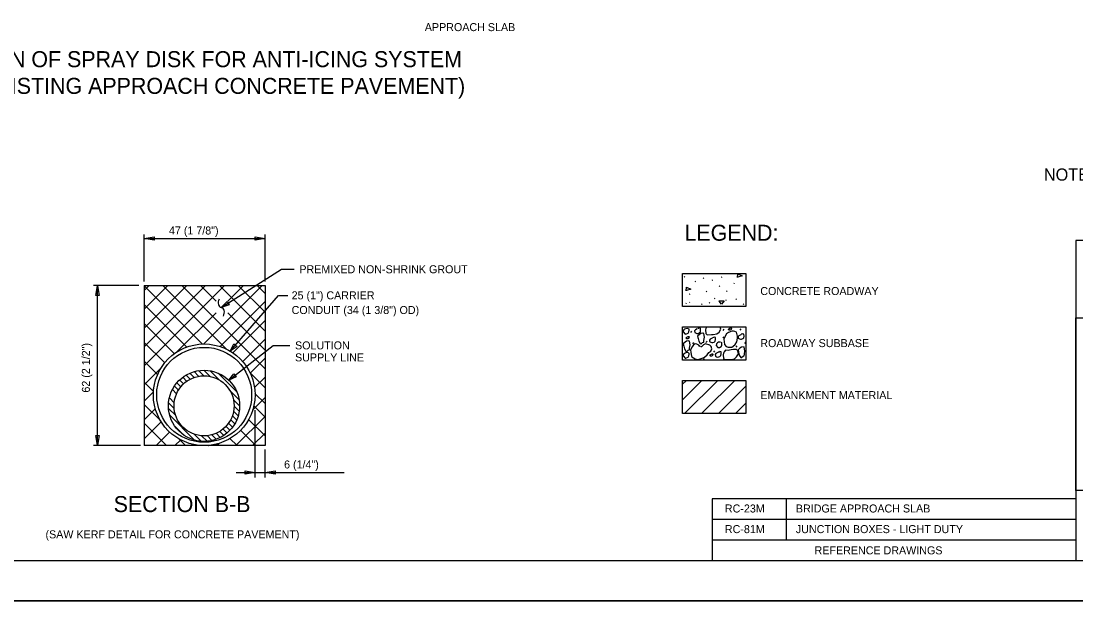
# Model space of a CAD drawing. Extents: x 3239 to 4230, y -4276 to -2494.
# Drawn here: x 3469.7 to 3865, y -3689.8 to -3465.1 of the extents above; entities that cross this region are included whole.
import ezdxf

# ---------------------------------------------------------------- set-up
doc = ezdxf.new("R2010")
doc.units = 0
for name, color, linetype in [('1', 7, 'Continuous'), ('2', 7, 'Continuous'), ('40', 7, 'Continuous'), ('PLT-BNDY', 7, 'Continuous')]:
    doc.layers.add(name, color=color, linetype=linetype)

msp = doc.modelspace()

# ---------------------------------------------------------------- linework, layer by layer
at = {"layer": '1'}
for p, q in [((4065.03, -3547.29), (3865.03, -3547.29)), ((3865.03, -3547.29), (3865.03, -3667.29)), ((3865.03, -3640.93), (3865.03, -3576.25)), ((3865.03, -3576.25), (4065.03, -3576.25)), ((4065.03, -3640.93), (3865.03, -3640.93))]:
    msp.add_line(p, q, dxfattribs=at)
at = {"layer": '2'}
for p, q in [((3515.85, -3562.63), (3515.85, -3545.01)), ((3561.14, -3562.63), (3561.14, -3545.01)), ((3515.85, -3546.51), (3561.14, -3546.51)), ((3718.22, -3560.98), (3718.46, -3560.79)), ((3725.33, -3561.46), (3725.56, -3561.27)), ((3732.2, -3561.05), (3732.44, -3560.87)), ((3513.9, -3564.13), (3496.86, -3564.13)), ((3498.36, -3624.13), (3498.36, -3564.13)), ((3515.85, -3564.13), (3561.14, -3564.13)), ((3515.85, -3564.13), (3515.85, -3624.13)), ((3515.85, -3565.94), (3517.66, -3564.13)), ((3515.85, -3573.01), (3524.73, -3564.13)), ((3515.85, -3580.08), (3531.8, -3564.13)), ((3515.85, -3587.16), (3538.87, -3564.13)), ((3515.85, -3594.23), (3545.94, -3564.13)), ((3537.7, -3586.08), (3515.85, -3564.22)), ((3546.66, -3587.96), (3522.82, -3564.13)), ((3561.14, -3595.38), (3529.9, -3564.13)), ((3542.83, -3569.99), (3536.97, -3564.13)), ((3538.18, -3586.03), (3560.09, -3564.13)), ((3561.14, -3581.24), (3544.04, -3564.13)), ((3547.14, -3570), (3553.01, -3564.13)), ((3561.14, -3574.17), (3551.11, -3564.13)), ((3561.14, -3567.09), (3558.18, -3564.13)), ((3561.14, -3564.13), (3561.14, -3624.13)), ((3722.34, -3562.65), (3722.57, -3562.46)), ((3728.68, -3562.16), (3728.91, -3561.97)), ((3731.29, -3564.48), (3731.53, -3564.29)), ((3736.91, -3563.34), (3737.14, -3563.15)), ((3720.22, -3567.38), (3720.45, -3567.19)), ((3726.42, -3566.46), (3726.66, -3566.27)), ((3729.55, -3569.04), (3729.78, -3568.85)), ((3733.83, -3569.63), (3734.07, -3569.44)), ((3734.1, -3566.37), (3734.33, -3566.18)), ((3737.61, -3569.35), (3737.84, -3569.16)), ((3531.79, -3587.24), (3515.85, -3571.29)), ((3544.28, -3587.01), (3561.14, -3570.14)), ((3718.91, -3570.83), (3719.14, -3570.64)), ((3720.17, -3570.55), (3720.4, -3570.36)), ((3724.75, -3571.18), (3724.98, -3570.99)), ((3727.55, -3570.69), (3727.78, -3570.5)), ((3740.35, -3571.19), (3740.58, -3571.01)), ((3528.14, -3589), (3542.83, -3574.32)), ((3561.14, -3588.31), (3547.14, -3574.31)), ((3549.03, -3589.33), (3561.14, -3577.21)), ((3527.18, -3589.7), (3515.85, -3578.36)), ((3552.77, -3592.65), (3561.14, -3584.28)), ((3523.54, -3593.13), (3515.85, -3585.44)), ((3520.86, -3597.52), (3515.85, -3592.51)), ((3555.53, -3596.97), (3561.14, -3591.35)), ((3515.85, -3601.3), (3522.22, -3594.92)), ((3532.97, -3596.96), (3534.59, -3598.59)), ((3534.53, -3596.4), (3536.26, -3598.14)), ((3536.26, -3596.01), (3538.21, -3597.96)), ((3538.23, -3595.86), (3540.56, -3598.19)), ((3540.54, -3596.05), (3544, -3599.51)), ((3543.55, -3596.94), (3550.55, -3603.94)), ((3561.14, -3602.45), (3555.39, -3596.7)), ((3519.38, -3603.84), (3515.85, -3600.3)), ((3528.1, -3600.58), (3529.6, -3602.08)), ((3529.13, -3599.49), (3530.63, -3600.98)), ((3530.29, -3598.52), (3531.79, -3600.03)), ((3531.56, -3597.68), (3533.11, -3599.22)), ((3557.17, -3602.4), (3561.14, -3598.43)), ((3717.56, -3606.99), (3724.89, -3599.66)), ((3717.56, -3601.14), (3719.04, -3599.66)), ((3718.39, -3612.07), (3730.79, -3599.66)), ((3725.69, -3611.13), (3737.16, -3599.66)), ((3515.85, -3607.42), (3519.29, -3603.98)), ((3519.29, -3602.83), (3519.44, -3602.68)), ((3526.41, -3603.13), (3527.99, -3604.71)), ((3527.19, -3601.79), (3528.71, -3603.31)), ((3547.96, -3603.47), (3551.44, -3606.95)), ((3561.14, -3608.3), (3557.38, -3604.53)), ((3731.11, -3612.07), (3741.31, -3601.87)), ((3522.05, -3614.87), (3515.85, -3608.66)), ((3524.99, -3608.08), (3527.09, -3610.18)), ((3525.28, -3606.24), (3527.11, -3608.08)), ((3549.31, -3606.94), (3551.63, -3609.26)), ((3556.44, -3610.84), (3561.14, -3606.14)), ((3737.48, -3612.07), (3741.31, -3608.24)), ((3515.85, -3614.44), (3520.05, -3610.24)), ((3524.98, -3610.19), (3527.67, -3612.88)), ((3525.43, -3612.76), (3534.73, -3622.06)), ((3548.9, -3612.9), (3550.53, -3614.52)), ((3549.35, -3611.23), (3551.09, -3612.96)), ((3549.54, -3609.29), (3551.48, -3611.23)), ((3561.14, -3613.4), (3556.93, -3609.18)), ((3557.39, -3636.11), (3557.39, -3610.8)), ((3724.75, -3612.07), (3725.85, -3610.96)), ((3515.85, -3621.51), (3522.22, -3615.14)), ((3524.24, -3624.13), (3515.85, -3615.73)), ((3527.27, -3616.72), (3530.77, -3620.22)), ((3546.51, -3616.86), (3548, -3618.35)), ((3547.46, -3615.7), (3548.97, -3617.2)), ((3548.26, -3614.38), (3549.81, -3615.93)), ((3550.22, -3624.13), (3561.14, -3613.21)), ((3561.14, -3620.47), (3554.98, -3614.31)), ((3520.3, -3624.13), (3525.42, -3619.01)), ((3534.61, -3619.82), (3537.3, -3622.51)), ((3537.31, -3620.4), (3539.41, -3622.5)), ((3539.41, -3620.38), (3541.25, -3622.21)), ((3541.21, -3620.06), (3542.88, -3621.73)), ((3542.78, -3619.5), (3544.36, -3621.08)), ((3544.18, -3618.78), (3545.7, -3620.3)), ((3545.41, -3617.89), (3546.91, -3619.39)), ((3557.73, -3624.13), (3551.95, -3618.35)), ((3556.48, -3624.13), (3561.14, -3619.46)), ((3514.5, -3624.13), (3496.86, -3624.13)), ((3561.14, -3624.13), (3515.85, -3624.13)), ((3527.37, -3624.13), (3529.56, -3621.94)), ((3531.31, -3624.13), (3528.65, -3621.46)), ((3533.46, -3624.13), (3533.97, -3623.61)), ((3539.83, -3624.13), (3539.92, -3624.04)), ((3543.59, -3624.13), (3542.97, -3623.51)), ((3543.15, -3624.13), (3544.06, -3623.22)), ((3550.66, -3624.13), (3547.98, -3621.45)), ((3557.3, -3624.13), (3557.39, -3624.04)), ((3561.14, -3636.11), (3561.14, -3625.52)), ((3550.32, -3634.17), (3590.82, -3634.17)), ((3728.73, -3644.08), (3728.73, -3667.29)), ((3865.03, -3644.08), (3728.73, -3644.08)), ((3756.39, -3644.08), (3756.39, -3659.55)), ((3865.03, -3651.82), (3728.73, -3651.82)), ((3865.03, -3659.55), (3728.73, -3659.55)), ((4065.03, -3667.29), (3279.03, -3667.29))]:
    msp.add_line(p, q, dxfattribs=at)
for points in [[(3519.6, -3547.14), (3515.85, -3546.51), (3519.6, -3545.88)], [(3557.39, -3545.88), (3561.14, -3546.51), (3557.39, -3547.14)], [(3717.56, -3559.63), (3741.31, -3559.63), (3741.31, -3572.04), (3717.56, -3572.04)], [(3497.73, -3567.88), (3498.36, -3564.13), (3498.99, -3567.88)], [(3547.69, -3571.38), (3544.75, -3572.36), (3546.89, -3570.12)], [(3717.56, -3579.65), (3741.31, -3579.65), (3741.31, -3592.05), (3717.56, -3592.05)], [(3550.64, -3586.95), (3548.1, -3588.72), (3549.5, -3585.97)], [(3550.38, -3598.34), (3547.56, -3599.6), (3549.46, -3597.16)], [(3717.56, -3599.66), (3741.31, -3599.66), (3741.31, -3612.07), (3717.56, -3612.07)], [(3498.99, -3620.38), (3498.36, -3624.13), (3497.73, -3620.38)], [(3553.64, -3633.54), (3557.39, -3634.17), (3553.64, -3634.8)], [(3564.89, -3634.8), (3561.14, -3634.17), (3564.89, -3633.54)]]:
    msp.add_lwpolyline(points, close=True, dxfattribs=at)
for points in [[(3544.75, -3572.36), (3567.32, -3558.04), (3572.09, -3558.04)], [(3738.18, -3561.07), (3738.32, -3559.72), (3739.95, -3560.47), (3738.3, -3560.96)], [(3718.98, -3566.1), (3719.12, -3564.75), (3720.75, -3565.49), (3719.1, -3565.98)], [(3548.1, -3588.72), (3566.2, -3567.93), (3569.63, -3567.93)], [(3731.23, -3569.86), (3733.16, -3569.88), (3732.19, -3571.14), (3731.37, -3570)], [(3719.59, -3580.27), (3718.83, -3580.33), (3718.39, -3580.52), (3717.98, -3580.86), (3717.88, -3581.48), (3718.55, -3582.32), (3718.85, -3582.29), (3719.15, -3582.27), (3719.73, -3581.93), (3719.87, -3581.77), (3719.99, -3581.45), (3720.09, -3580.83), (3720.07, -3580.53), (3719.9, -3580.39), (3719.74, -3580.25)], [(3721.01, -3581.19), (3720.6, -3581.69)], [(3723.15, -3580.4), (3722.42, -3580.76), (3722.15, -3581.09), (3722.2, -3581.7), (3722.68, -3581.96), (3723, -3582.09), (3723.45, -3582.05), (3723.89, -3581.86), (3724.3, -3581.51), (3724.4, -3580.9), (3724.33, -3580.14), (3723.88, -3580.03), (3723.59, -3580.2), (3723.29, -3580.23)], [(3726.64, -3579.65), (3726.6, -3579.69), (3726.34, -3580.17), (3726.24, -3580.77), (3726.36, -3582.13), (3726.85, -3582.55), (3728.51, -3582.53), (3729.11, -3582.48), (3730.44, -3582.23), (3731.3, -3581.55), (3731.94, -3580.43), (3731.77, -3579.65)], [(3733.06, -3580.49), (3732.65, -3580.98)], [(3735.84, -3581.37), (3734.83, -3581.76), (3734.11, -3582.26), (3733.45, -3583.39), (3733.06, -3584.18), (3733.39, -3586.27), (3733.91, -3586.99), (3734.69, -3587.2), (3735.59, -3587.27), (3736.05, -3587.23), (3736.63, -3586.88), (3737.33, -3586.23), (3737.99, -3585.26), (3738.17, -3583.89), (3738.26, -3583.12), (3737.83, -3581.65), (3737.22, -3581.4), (3736.75, -3581.29), (3736.13, -3581.19)], [(3739.44, -3580.31), (3739.02, -3580.81)], [(3719.91, -3584.89), (3719.15, -3584.96), (3718.57, -3585.31), (3717.87, -3585.98), (3718.1, -3586.86), (3718.34, -3587.9), (3718.87, -3588.77), (3719.19, -3588.9), (3719.75, -3588.39), (3720.2, -3588.2), (3720.27, -3587.58), (3720.47, -3586.36), (3720.2, -3585.02), (3720.03, -3584.88)], [(3725.25, -3582.03), (3724.49, -3582.09), (3723.92, -3582.45), (3723.21, -3583.12), (3723.44, -3583.99), (3723.68, -3585.04), (3724.22, -3585.91), (3724.53, -3586.03), (3725.1, -3585.53), (3725.54, -3585.33), (3725.62, -3584.72), (3725.82, -3583.5), (3725.55, -3582.15), (3725.38, -3582.01)], [(3726.8, -3585), (3726.39, -3585.49)], [(3728.72, -3583.85), (3727.99, -3584.22), (3727.72, -3584.55), (3727.77, -3585.15), (3728.25, -3585.41), (3728.57, -3585.54), (3729.02, -3585.5), (3729.46, -3585.31), (3729.87, -3584.97), (3729.97, -3584.35), (3729.9, -3583.59), (3729.45, -3583.48), (3729.16, -3583.66), (3728.86, -3583.68)], [(3731.88, -3585.33), (3731.12, -3585.39), (3730.68, -3585.59), (3730.28, -3585.92), (3730.18, -3586.54), (3730.84, -3587.38), (3731.14, -3587.35), (3731.45, -3587.33), (3732.03, -3586.99), (3732.17, -3586.83), (3732.29, -3586.51), (3732.39, -3585.89), (3732.36, -3585.59), (3732.2, -3585.45), (3732.03, -3585.31)], [(3733.06, -3583.3), (3732.65, -3583.79)], [(3739.45, -3582.56), (3738.72, -3582.93), (3738.44, -3583.26), (3738.49, -3583.86), (3738.97, -3584.13), (3739.29, -3584.25), (3739.74, -3584.21), (3740.18, -3584.02), (3740.59, -3583.68), (3740.69, -3583.06), (3740.62, -3582.31), (3740.18, -3582.19), (3739.89, -3582.37), (3739.59, -3582.4)], [(3547.56, -3599.6), (3564.2, -3586.56), (3570.46, -3586.56)], [(3719.59, -3589.28), (3718.83, -3589.34), (3718.39, -3589.54), (3717.98, -3589.87), (3717.88, -3590.49), (3718.55, -3591.33), (3718.85, -3591.3), (3719.15, -3591.28), (3719.73, -3590.94), (3719.87, -3590.78), (3719.99, -3590.46), (3720.09, -3589.84), (3720.07, -3589.54), (3719.9, -3589.4), (3719.74, -3589.26)], [(3724.4, -3587.07), (3723.92, -3586.81), (3723.74, -3586.52), (3722.97, -3586.13), (3722.35, -3586.03), (3721.77, -3586.39), (3721.22, -3587.04), (3720.58, -3588.17), (3720.67, -3589.2), (3720.94, -3590.55), (3721.11, -3590.82), (3722.38, -3591.63), (3723.47, -3591.84), (3724.63, -3591.43), (3725.37, -3591.21), (3725.81, -3591.02), (3726.78, -3590.04), (3727.47, -3589.22), (3728.18, -3588.7), (3728.55, -3587.9), (3728.32, -3587.03), (3727.84, -3586.46), (3726.27, -3585.99), (3725.41, -3586.37), (3724.7, -3587.04), (3724.55, -3587.06)], [(3721.71, -3585.46), (3721.3, -3585.96)], [(3729.59, -3588.56), (3729.18, -3589.05)], [(3730.86, -3589.25), (3730.13, -3589.62), (3729.85, -3589.95), (3729.9, -3590.55), (3730.38, -3590.82), (3730.7, -3590.94), (3731.16, -3590.9), (3731.6, -3590.71), (3732, -3590.37), (3732.1, -3589.75), (3732.03, -3589), (3731.59, -3588.88), (3731.3, -3589.06), (3731, -3589.09)], [(3734.65, -3588.43), (3733.73, -3588.35), (3733.2, -3589.01), (3732.93, -3589.49), (3732.83, -3590.09), (3732.95, -3591.45), (3733.45, -3591.87), (3735.1, -3591.85), (3735.71, -3591.8), (3737.04, -3591.55), (3737.89, -3590.87), (3738.53, -3589.74), (3738.28, -3588.57), (3737.81, -3588.15), (3736.73, -3588.09), (3735.82, -3588.17), (3735.25, -3588.37), (3734.65, -3588.43)], [(3737.97, -3586.69), (3737.56, -3587.19)], [(3740.44, -3587.16), (3739.69, -3587.22), (3739.11, -3587.58), (3738.4, -3588.25), (3738.63, -3589.12), (3738.88, -3590.17), (3739.41, -3591.04), (3739.73, -3591.16), (3740.29, -3590.66), (3740.73, -3590.46), (3740.81, -3589.85), (3741.01, -3588.63), (3740.74, -3587.28), (3740.57, -3587.14)], [(3741.25, -3585.41), (3740.83, -3585.9)], [(3725.72, -3591.44), (3725.3, -3591.93)]]:
    msp.add_lwpolyline(points, dxfattribs=at)
for centre, radius in [((3538.34, -3605.08), 19.05), ((3538.34, -3605.08), 17.79), ((3538.29, -3609.2), 13.34), ((3538.29, -3609.2), 11.25)]:
    msp.add_circle(centre, radius, dxfattribs=at)
for centre, major_axis, start_param in [((3545.21, -3570.21), (0.62, 2.11), 1.293816), ((3544.29, -3574.5), (-0.62, -2.11), 1.265473)]:
    msp.add_ellipse(centre, major_axis=major_axis, ratio=0.707981, start_param=start_param, end_param=3.248243, dxfattribs=at)
for points in [[(3735.88, -3580.4), (3735.81, -3580.6), (3735.65, -3580.77), (3735.23, -3580.87), (3734.97, -3580.72), (3734.88, -3580.46), (3735.15, -3580.29), (3735.65, -3580.03), (3735.96, -3580.06), (3735.88, -3580.42)], [(3719.99, -3583.63), (3719.92, -3583.83), (3719.76, -3584), (3719.33, -3584.1), (3719.08, -3583.95), (3718.99, -3583.7), (3719.26, -3583.52), (3719.76, -3583.26), (3720.06, -3583.3), (3719.99, -3583.65)], [(3728.9, -3590.14), (3728.83, -3590.34), (3728.67, -3590.51), (3728.24, -3590.61), (3727.99, -3590.46), (3727.9, -3590.21), (3728.17, -3590.03), (3728.67, -3589.77), (3728.98, -3589.81), (3728.9, -3590.16)]]:
    msp.add_spline(points, degree=3, dxfattribs=at)
at = {"layer": 'PLT-BNDY'}
for points in [[(3239.03, -3088.29), (4080.03, -3088.29), (4080.03, -3682.29), (3239.03, -3682.29)], [(3239.03, -3682.29), (4080.03, -3682.29), (4080.03, -4276.29), (3239.03, -4276.29)]]:
    msp.add_lwpolyline(points, close=True, dxfattribs=at)

# ---------------------------------------------------------------- texts
at = {"layer": '2'}
for s, height, p in [('APPROACH SLAB', 3, (3621.02, -3468.81)), ('INSTALLATION OF SPRAY DISK FOR ANTI-ICING SYSTEM ', 6, (3414.27, -3482.32)), ('(EXISTING APPROACH CONCRETE PAVEMENT)', 6, (3452.49, -3492.32)), ('47 (1 7/8")', 3, (3525.13, -3545.01)), ('LEGEND:', 6, (3718.33, -3547.35)), ('PREMIXED NON-SHRINK GROUT', 3, (3574, -3559.54)), ('CONCRETE ROADWAY', 3, (3746.75, -3567.7)), ('25 (1") CARRIER', 3, (3571.11, -3569.31)), ('CONDUIT (34 (1 3/8") OD)', 3, (3571.11, -3574.81)), ('SOLUTION', 3, (3572.39, -3588.06)), ('ROADWAY SUBBASE', 3, (3746.75, -3587.2)), ('SUPPLY LINE', 3, (3572.39, -3592.56)), ('EMBANKMENT MATERIAL', 3, (3746.75, -3606.7)), ('6 (1/4")', 3, (3568.28, -3632.67)), ('SECTION B-B', 6, (3504.41, -3649.02)), ('RC-23M', 3, (3733.48, -3649.17)), ('BRIDGE APPROACH SLAB', 3, (3760.08, -3649.17)), ('(SAW KERF DETAIL FOR CONCRETE PAVEMENT)', 3, (3478.87, -3658.86)), ('RC-81M', 3, (3733.48, -3656.9)), ('JUNCTION BOXES - LIGHT DUTY', 3, (3760.08, -3656.9)), ('REFERENCE DRAWINGS', 3, (3767.09, -3664.86))]:
    msp.add_text(s, height=height, dxfattribs=at).set_placement(p)
msp.add_text('62 (2 1/2")', height=3, rotation=90, dxfattribs=at).set_placement((3495.51, -3604.25))
at = {"layer": '40'}
msp.add_text('NOTE: EITHER ALL METRIC OR ALL ENGLISH VALUES', height=4.5587, dxfattribs=at).set_placement((3853.02, -3524.83))

doc.saveas('drawing.dxf')
